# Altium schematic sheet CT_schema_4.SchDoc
size 143 x 108 mm
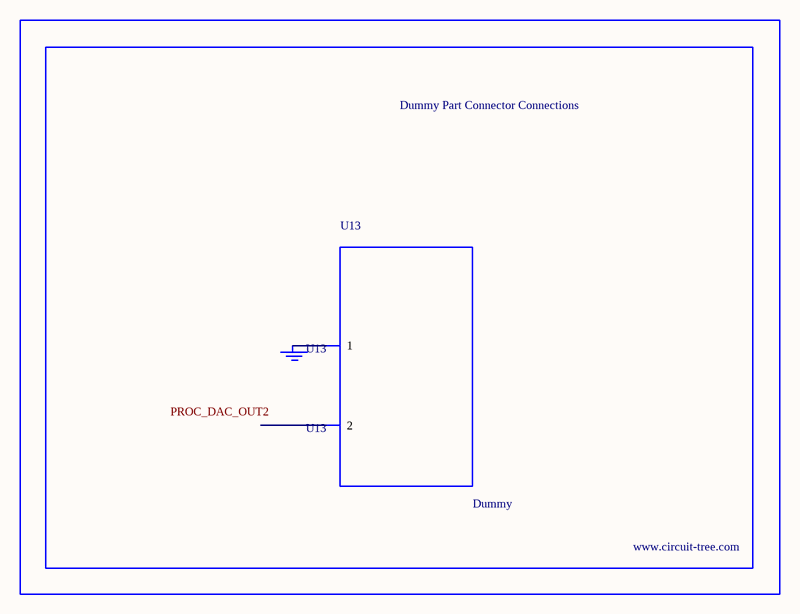
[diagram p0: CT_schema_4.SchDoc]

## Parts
BORDER3  (no value)
GND_INSTANCE_3_0  (no value)
U13  Dummy  [DUMMY_PACKAGE_115]

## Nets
NetGND_INSTANCE_3_0_0: GND_INSTANCE_3_0.0(GND) U13.1

Not connected (* = marked no-connect by the designer): U13 2

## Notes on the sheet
- Labels drawn without touching a wire or pin: PROC_DAC_OUT2

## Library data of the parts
BORDER3 = BORDER_PAGE3
GND_INSTANCE_3_0 = GND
